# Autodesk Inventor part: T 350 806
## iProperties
Company: Mayer & Müller AG Schaltgeräte
Created: 2005-12
Part Number: T 350 806
Material: 2.0060.30
Document SubType Name: Modeling
Designer: I.Baliuc
Manufacturer: Standard
Standards Organization: Custom
Description: Funkenhorn
Density: 8.94 g/cm^3
HalbzeugNorm: DIN 1759
Zweck: fest
Abmessung: 120 x 15
Author: T.Messerschmitt
Revision Number: 350806
Keywords: 382024
Comments: Extrusion2 geändert für die zeichnung für Berlin Prüf.: 4,6 + 3,4
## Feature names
1. Extrusion2
2. Bohrung_M8 [Hole]
3. Bohrung_M5 [Hole]
4. Bohrung3 [Hole]
5. Fase1 [Chamfer]
